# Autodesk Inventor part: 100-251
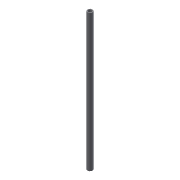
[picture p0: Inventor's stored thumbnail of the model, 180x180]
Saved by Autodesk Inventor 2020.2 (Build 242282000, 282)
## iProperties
Created: 2011-01
Part Number: 100-251
Document SubType Name: Modeling
Designer: F.Stasiak
Density: 1 g/cm^3
Material: Ogólny
Appearance: Domyślna
Company: Fabian Stasiak CAD Consulting
Manager: www.cadconsulting.pl
Author: F.Stasiak
Subject: Zbiór ćwiczeń. Autodesk Inventor 2020. Kurs podstawowy
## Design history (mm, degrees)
sketch "Szkic1"
  geometry: C1 r 40 at (0, 0); C2 r 30 at (0, 0); 1 further point
  constraints: 2 centre point, 2 coincident
  dimensions: "d0" = 80 diameter of C1; "d1" = 60 diameter of C2
extrude "Wyciągnięcie proste1" new body sketch "Szkic1" distance "d2" = 2150; taper "d3" = 0 deg
node "Bryła1"
